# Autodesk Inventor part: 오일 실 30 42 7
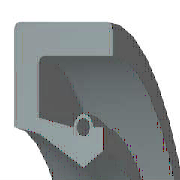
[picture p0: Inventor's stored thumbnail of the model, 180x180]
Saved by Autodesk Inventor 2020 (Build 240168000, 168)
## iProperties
Created: 2012-02
Part Number: 오일 실 30 42 7
Material: 고무
Description: 오일 실 - 스프링 장착, 금속 케이스 SM
Document SubType Name: Modeling
Standard: JIS B 2402
Designer: mdu-01
Standards Organization: JIS
Language: ko-KR
Size Designation: 30 42 7 A
Categories: <MemberInstance><Categories><Category DisplayName="샤프트 부품" InternalName="7f7aeb1f-a693-4053-b835-cee3144e0d98" Mnemonic="SHFT"><Category DisplayName="실링" Intern
Density: 0.93 g/cm^3
Appearance: Rubber-Black
IsCustomPart: 1
Author: mdu-01
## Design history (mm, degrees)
body "Solid1"
revolve "회전1" stored, may be unused: angle "d33" = 360 deg
fillet "모깎기1" dims "d34" = 0.35 (= 0.05 x b)
chamfer "모따기1" distance "d35" = 0.7 (= 0.1 x b); stored, may be unused: second distance "d36" = 0.35 (= 0.05 x b), angle "d41" = 45 deg
sketch "스케치2"
  geometry: L1 (16.457, -5.158)-(17.021, -7); L2 (15.857, -4.55)-(16.457, -5.158); L3 (15, -1.75)-(15.857, -4.55); L4 (15.8, -0.875)-(15, -1.75); L5 (17.141, -0.875)-(15.8, -0.875); L6 (17.141, -1.575)-(17.141, -0.875); L7 (17.141, -5.25)-(17.141, -2.975); L8 (18.6, -5.25)-(17.141, -5.25); L9 (19.8, -1.75)-(18.6, -5.25); L10 (19.8, 0)-(19.8, -1.75); L11 (21, 0)-(19.8, 0); L12 (21, -7)-(21, 0); L13 (17.021, -7)-(21, -7); L14 (0, -9.6)-(0, 1.6) reference; L15 (28, 0)-(14, 0) reference; A1 r 0.7 centre (17.141, -2.275) between (17.141, -2.975) and (17.141, -1.575)
  constraints: 26 end point, 4 horizontal, 4 vertical, 2 point on circle, 1 centre point, 1 collinear, 1 parallel
  dimensions: "d2" = 7 distance of L12.start L11.start (= b); "d4" = 0.875 vertical distance of L10.start L5.start (= 0.125 x b); "d6" = 1.2 distance of L11.start L10.start (= 0.1 x dd - 0.1 x Diam); "d8" = 1.75 distance of L10.start L9.start (= 0.25 x b); "d10" = 1.75 vertical distance of L8.start L1.end (= 0.25 x b); "d12" = 1.2 horizontal distance of L9.start L8.start (= 0.1 x dd - 0.1 x Diam); "d14" = 0.7 radius of A1 (= 0.1 x b); "d16" = 0 horizontal distance of A1.centre L7.end; "d18" = 0.7 distance of L6.start L5.start (= 0.1 x b); "d20" = 0.8 horizontal distance of L4.start L3.start (= 0.0666667 x dd - 0.0666667 x Diam); "d22" = 0.12 horizontal distance of L7.start L1.end (= 0.01 x dd - 0.01 x Diam); "d24" = 0.875 vertical distance of L4.start L3.start (= 0.125 x b); "d26" = 2.8 vertical distance of L3.start L2.start (= 0.4 x b); "d28" = 0.85714 horizontal distance of L3.start L2.start (= 0.0714286 x dd - 0.0714286 x Diam); "d30" = 1.84211 vertical distance of L1.start L1.end (= 0.263158 x b); "d32" = 0.6 horizontal distance of L2.start L1.start (= 0.05 x dd - 0.05 x Diam); "d37" = 0 distance between parallel lines of L15 L11; "d38" = 21 distance between parallel lines of L14 L12 (= 0.5 x dd); "d39" = 15 distance from line of L14 L3.start (= 0.5 x Diam)
other parameters: "dd" = 42 [user parameter; used in 7 equation terms], "b" = 7 [user parameter; used in 12 equation terms], "d1" = 8 (derived), "d3" = 1 (derived), "d5" = 2 (derived), "d7" = 2 (derived), "d9" = 2 (derived), "d11" = 2 (derived), "d13" = 0.8 (derived), "d15" = 0 (derived), "d17" = 0.8 (derived), "d19" = 1.33333 (derived), "d21" = 0.2 (derived), "d23" = 1 (derived), "d25" = 3.2 (derived), "d27" = 1.42857 (derived), "d29" = 2.10526 (derived), "d31" = 1 (derived), "d40" = 0
